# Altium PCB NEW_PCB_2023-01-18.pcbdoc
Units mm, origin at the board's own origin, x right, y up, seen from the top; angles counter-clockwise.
Board outline 125.93 x 125.98 mm, 2 copper layers (Top Layer, Bottom Layer); 36 components, 59 nets, 178 pads, 4 vias.
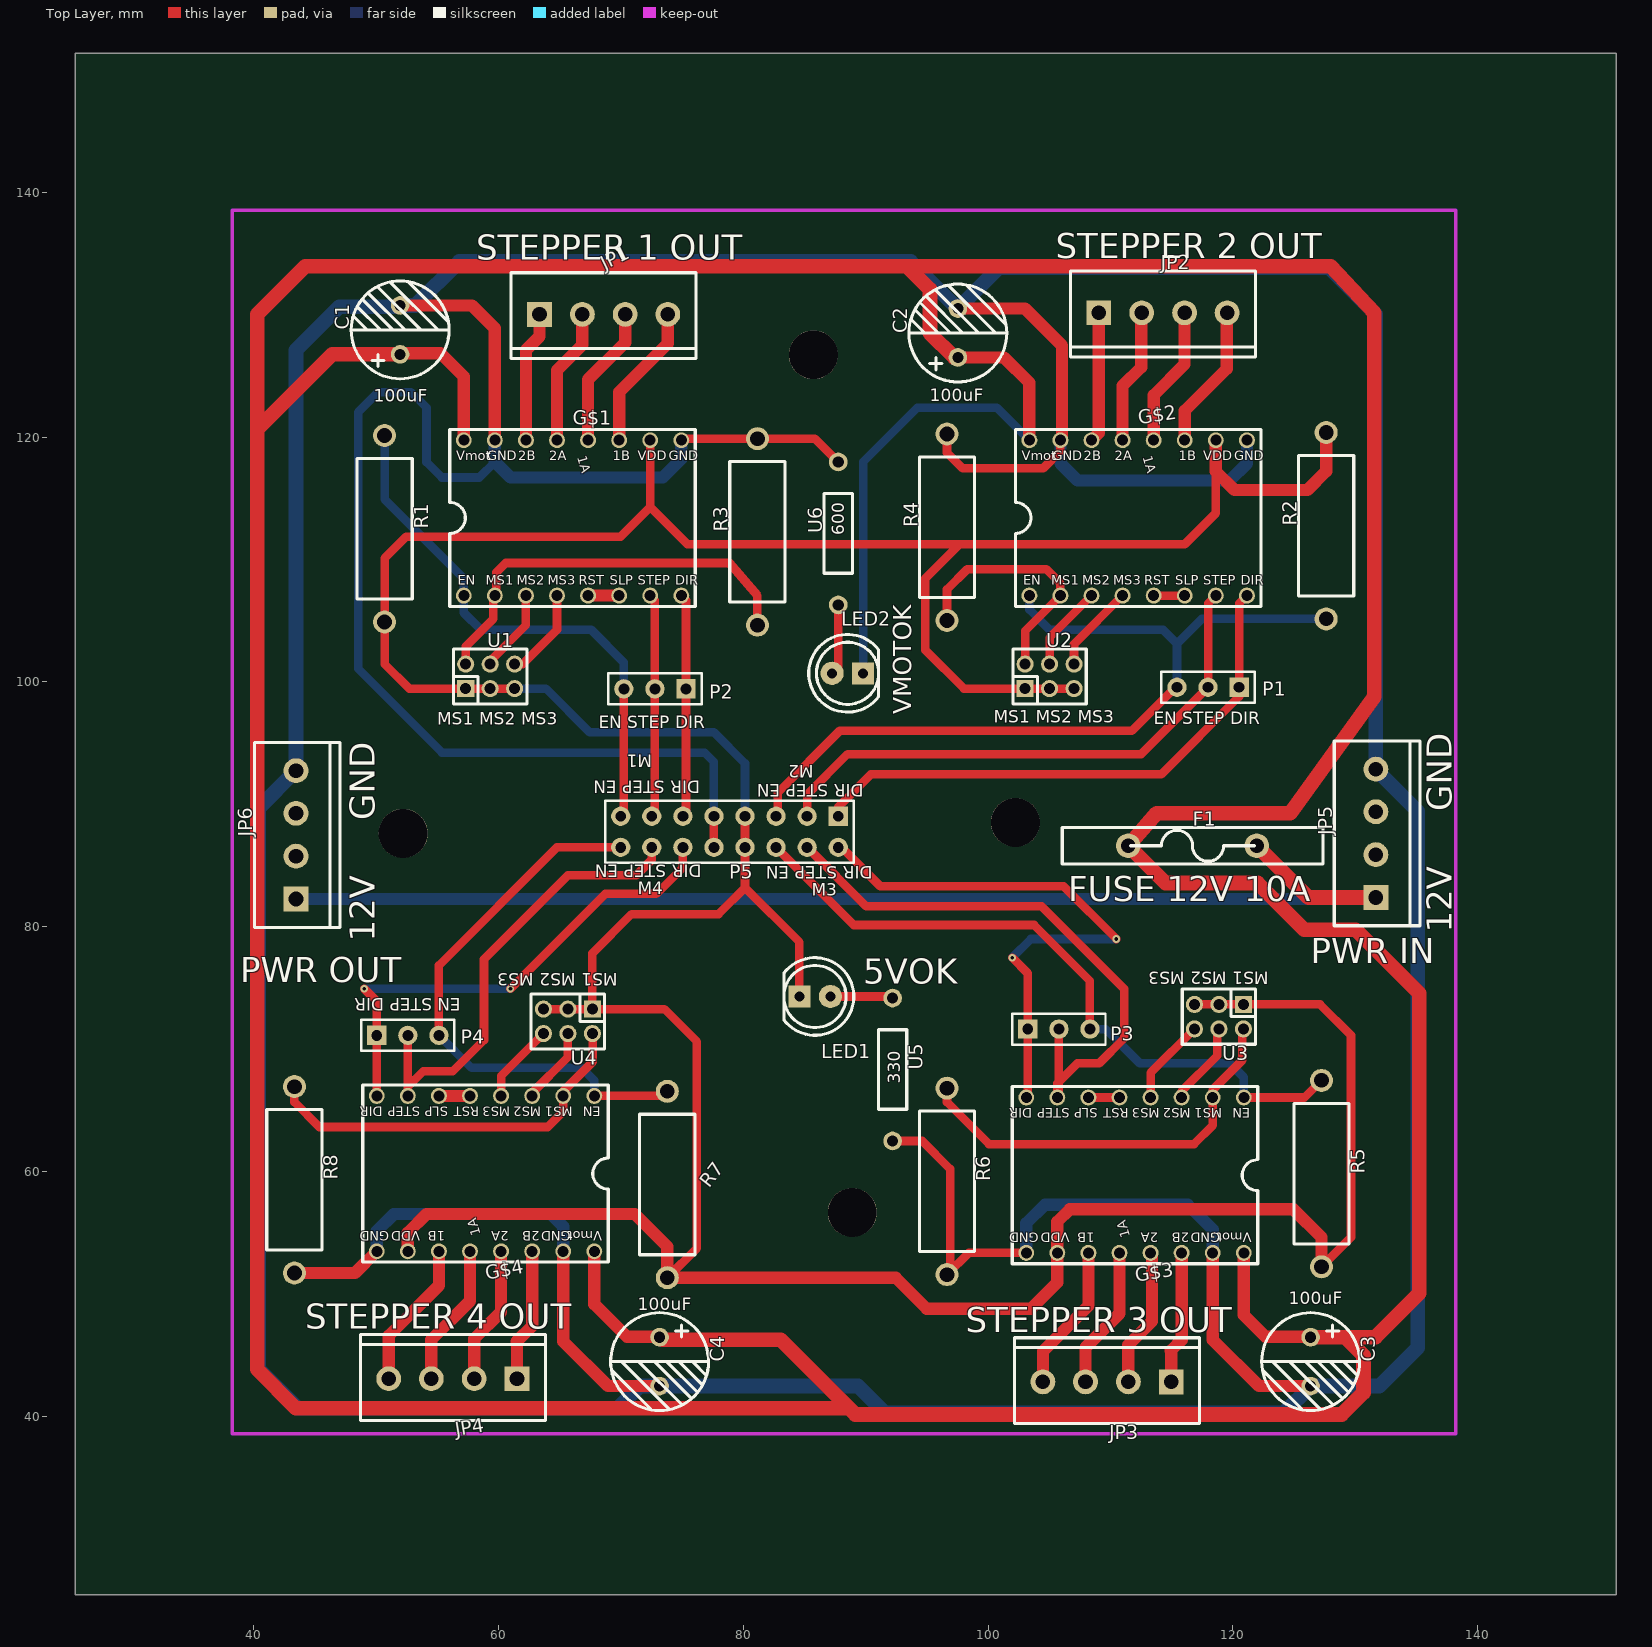
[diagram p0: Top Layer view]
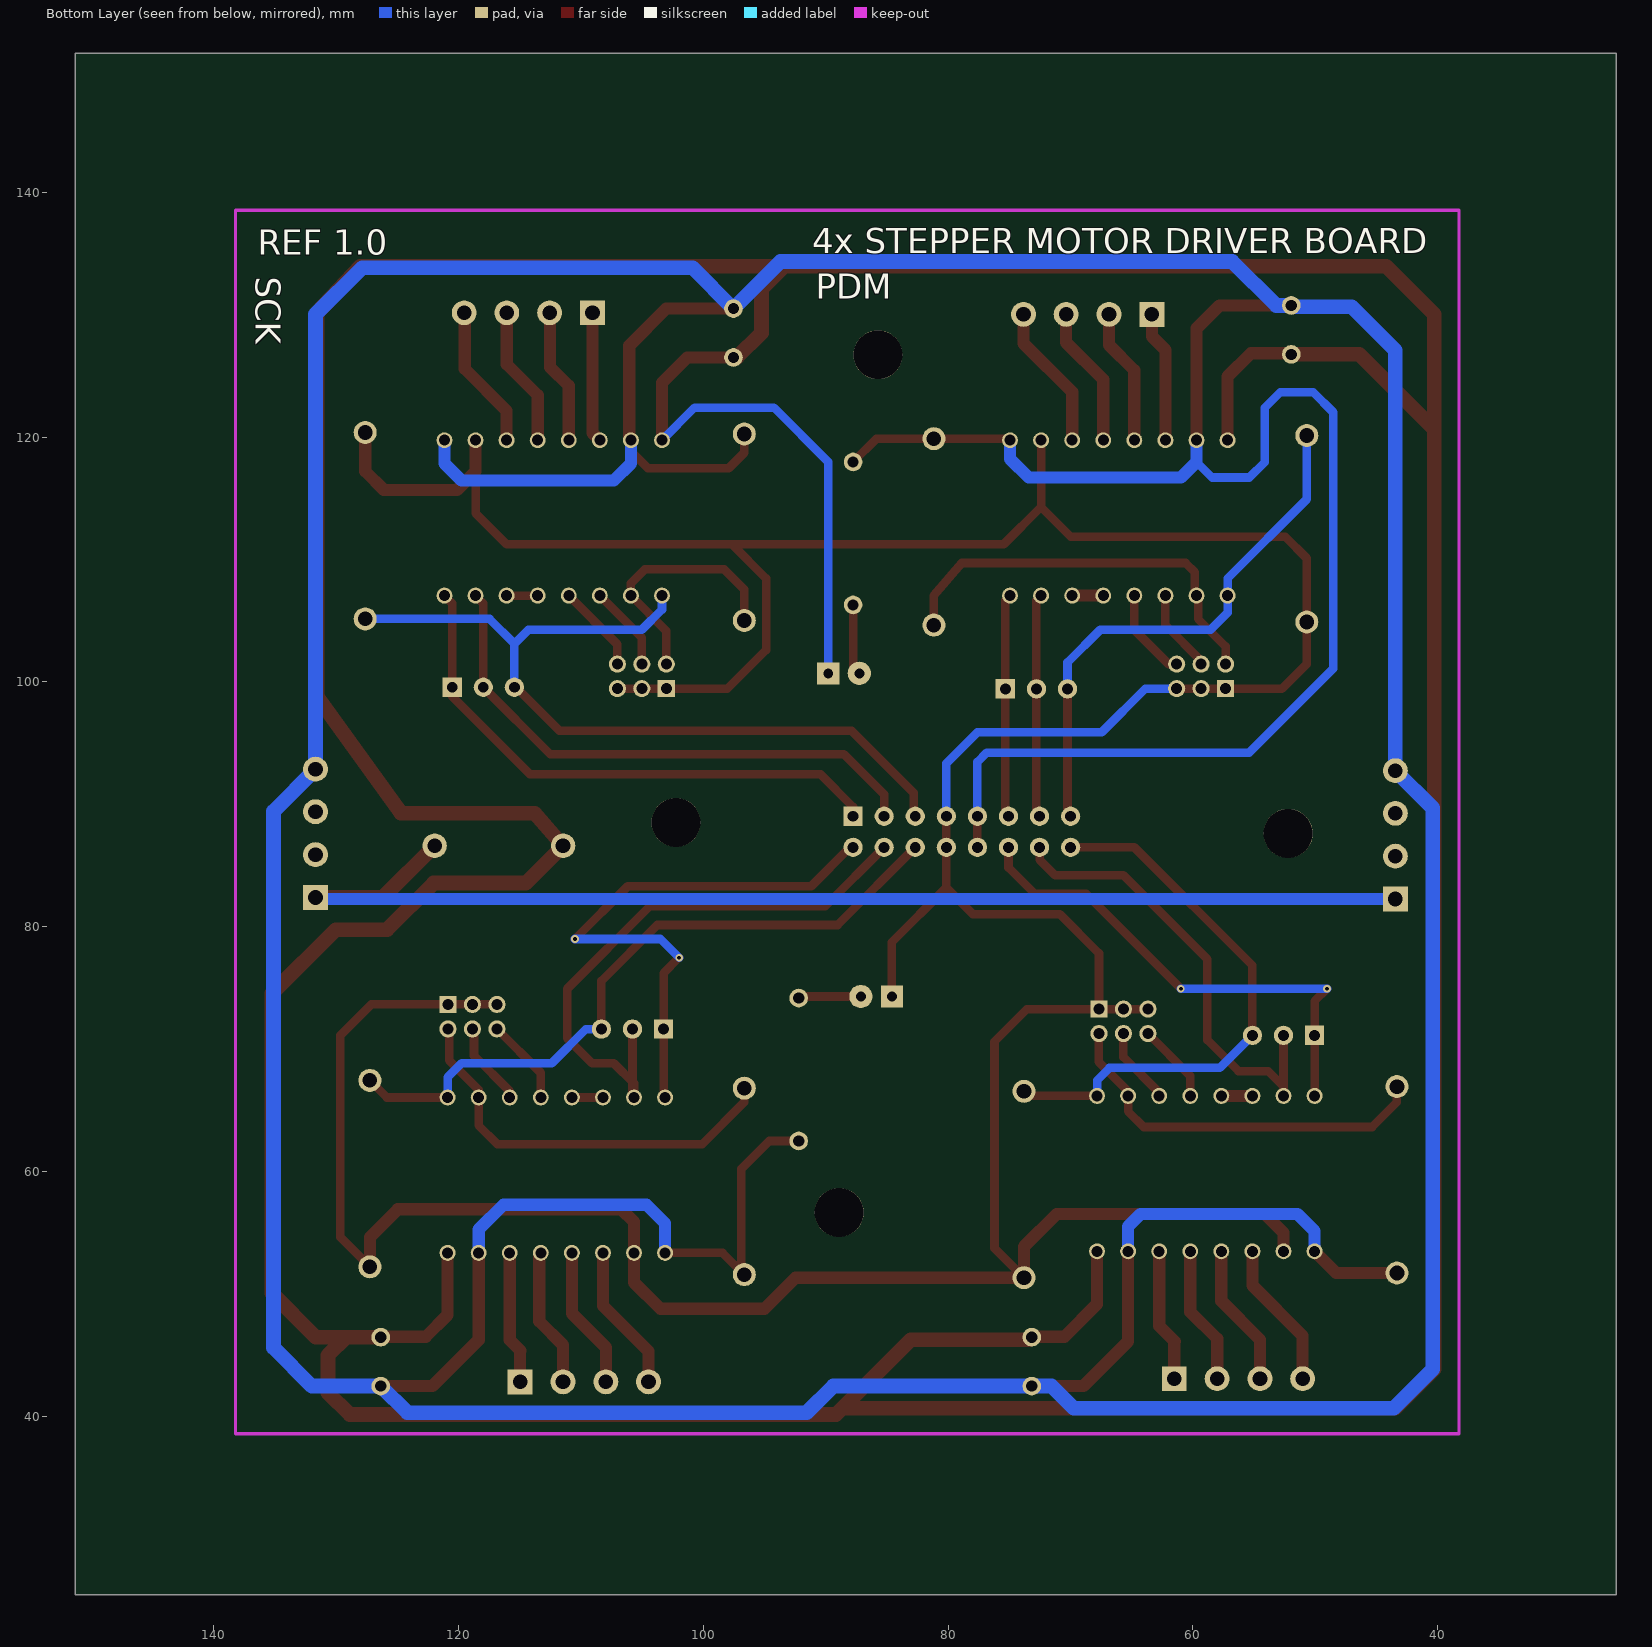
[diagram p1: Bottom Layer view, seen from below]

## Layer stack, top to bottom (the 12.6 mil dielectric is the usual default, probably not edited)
Top Layer: signal copper (thickness not stored)
Dielectric: dielectric 0.32, FR-4, Dk 4.8
Bottom Layer: signal copper (thickness not stored)

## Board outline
151.329,25.4 25.4,25.4 25.4,151.381 151.329,151.381

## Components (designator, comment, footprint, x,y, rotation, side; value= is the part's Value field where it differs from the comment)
C1 "100uF" CAP-8*5 51.943,128.775 r90 top
C2 "100uF" CAP-8*5 97.536,128.521 r90 top
C3 "100uF" CAP-8*5 126.365,44.447 r270 top
C4 "100uF" CAP-8*5 73.152,44.447 r270 top
F1 "fuseRXEF300" F-3.00A-60V 116.713,86.611 r0 top
G$1 "A4988" A4988BREAKOUT 58.42,118.488 r0 top
G$2 "A4988" A4988BREAKOUT 104.648,118.488 r0 top
G$3 "A4988" A4988BREAKOUT 119.634,54.607 r180 top
G$4 "A4988" A4988BREAKOUT 66.548,54.734 r180 top
JP1 "M04" SCREWTERMINAL-3.5MM-4 68.58,130.045 r0 top
JP2 "M04" SCREWTERMINAL-3.5MM-4 114.3,130.172 r0 top
JP3 "M04" SCREWTERMINAL-3.5MM-4 109.728,42.796 r180 top
JP4 "M04" SCREWTERMINAL-3.5MM-4 56.261,43.05 r180 top
JP5 "M04" SCREWTERMINAL-3.5MM-4 131.699,87.627 r90 top
JP6 "M04" SCREWTERMINAL-3.5MM-4 43.434,87.5 r90 top
LED1 "LED_5MM" "LED 5MM" 85.598,73.784 r180 top
LED2 "LED_5MM" "LED 5MM" 88.773,101.216 r0 top
P1 "Header-Male-2.54_1x3" HDR-3X1/2.54 117.983,99.565 r180 top
P2 "Header-Male-2.54_1x3" HDR-3X1/2.54 72.771,99.438 r180 top
P3 "Header-Male-2.54_1x3" HDR-3X1/2.54 105.791,71.625 r0 top
P4 "Header-Male-2.54_1x3" HDR-3X1/2.54 52.578,71.117 r0 top
P5 "Header-Male-2.54_2x8" HDR-8X2/2.54 78.867,87.754 r180 top
R1 "10k" AXIAL-0.6 50.673,112.519 r270 top
R2 "10k" AXIAL-0.6 127.635,112.773 r90 top
R3 "100k" AXIAL-0.6 81.153,112.265 r90 top
R4 "100k" AXIAL-0.6 96.647,112.646 r90 top
R5 "10k" AXIAL-0.6 127.254,59.814 r270 top
R6 "100k" AXIAL-0.6 96.647,59.179 r270 top
R7 "10k" AXIAL-0.6 73.787,58.925 r270 top
R8 "100k" AXIAL-0.6 43.307,59.306 r270 top
U1 "2*3P" HDR-2.0-2X3P 59.309,100.454 r0 top
U2 "2*3P" HDR-2.0-2X3P 105.029,100.454 r0 top
U3 "2*3P" HDR-2.0-2X3P 118.872,72.641 r180 top
U4 "2*3P" HDR-2.0-2X3P 65.659,72.26 r180 top
U5 "RF25CT52A331J" AXIAL-6.5X2.3(1/4W) 92.202,68.323 r270 top
U6 "RF25CT52A331J" AXIAL-6.5X2.3(1/4W) 87.757,112.138 r90 top

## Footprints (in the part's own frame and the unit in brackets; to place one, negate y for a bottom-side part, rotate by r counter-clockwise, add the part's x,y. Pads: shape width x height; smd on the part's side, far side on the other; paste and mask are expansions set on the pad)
A4988BREAKOUT [mm]
  round 1.3 hole 0.899: 1A(8.89,1.27) 1B(11.43,1.27) 2A(6.35,1.27) 2B(3.81,1.27) DIR(16.51,-11.43) EN(-1.27,-11.43) GND(16.51,1.27) GND@0(1.27,1.27) MS1(1.27,-11.43) MS2(3.81,-11.43) MS3(6.35,-11.43) RST(8.89,-11.43) SLP(11.43,-11.43) STEP(13.97,-11.43) VDD(13.97,1.27) VMOT(-1.27,1.27)
  silkscreen extent -2.41,-12.32 17.65,2.16
AXIAL-0.6 [mil]
  round 74 hole 47.2: 1(-300,0) 2(300,0)
  silkscreen extent -226,-89 226,89
AXIAL-6.5X2.3(1/4W) [mil]
  round 60 hole 36: 1(-230,0) 2(230,0)
  silkscreen extent -128,-45 128,45
CAP-8*5 [mil]
  round 60 hole 36: 1(-78.7,0) 2(78.7,0)
  silkscreen extent -158,-158 158,158
F-3.00A-60V [mm]
  round 2 hole 1.2: 1(-5.25,0) 2(5.25,0)
  silkscreen extent -10.65,-1.5 10.65,1.5
HDR-2.0-2X3P [mm]
  rect 1.4x1.4 hole 0.9: 1(-2,-1)
  round 1.4 hole 0.9: 2(-2,1) 3(0,-1) 4(0,1) 5(2,-1) 6(2,1)
  silkscreen extent -3,-2.25 3,2.25
HDR-3X1/2.54 [mil]
  rect 62x62 hole 35: 1(-100,0)
  round 62 hole 35: 2(0,0) 3(100,0)
  silkscreen extent -150,-50 150,50
HDR-8X2/2.54 [mil]
  rect 62x62 hole 35: 1(-350,-50)
  round 62 hole 35: 2(-350,50) 3(-250,-50) 4(-250,50) 5(-150,-50) 6(-150,50) 7(-50,-50) 8(-50,50) 9(50,-50) 10(50,50) 11(150,-50) 12(150,50) 13(250,-50) 14(250,50) 15(350,-50) 16(350,50)
  silkscreen extent -400,-100 400,100
"LED 5MM" [mm]
  round 1.9 hole 0.813: 1(-1.524,-0.508)
  rect 1.8x1.8 hole 0.813: 2(1.016,-0.507)
  silkscreen extent -3.42,-3.68 2.29,2.66
SCREWTERMINAL-3.5MM-4 [mil]
  rect 80x80 hole 47.2: 1(-206.5,0)
  round 80 hole 47.2: 2(-68.5,0) 3(69.5,0) 4(206.5,0)
  silkscreen extent -298,-142 298,134

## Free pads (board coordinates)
  round 4 hole 4 unplated: ""(52.197,87.627) ""(85.725,126.743) ""(88.9,56.639) ""(102.235,88.516)

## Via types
v1: diameter 0.62, hole 0.305, Top Layer to Bottom Layer, tented both sides, 4 vias

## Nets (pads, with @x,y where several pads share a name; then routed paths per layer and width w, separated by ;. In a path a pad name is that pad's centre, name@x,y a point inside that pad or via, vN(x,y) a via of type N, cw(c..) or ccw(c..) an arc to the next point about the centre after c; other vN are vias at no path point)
+5V: G$1.VDD G$2.VDD G$3.VDD G$4.VDD LED1.2 P5.7 P5.8 R1.2 R2.2 R5.2 R7.2 U1.1 U1.3 U1.5 U2.1 U2.3 U2.5 U3.1 U3.3 U3.5 U4.1 U4.3 U4.5 | length 381.6
  Top Layer w0.7: U1.5 U1.3 U1.1 52.721,99.454 52.705,99.438 50.673,101.47 R1.2 50.673,110.106 52.451,111.884 69.977,111.884 72.39,114.297 ; U4.5 U4.3 U4.1 ; G$1.VDD 72.39,114.297 ; R7.2 76.2,53.718 76.2,70.609 73.549,73.26 U4.1 ; P5.7 P5.8 80.137,83.182 ; LED1.2 84.582,78.738 80.137,83.182 ; U2.5 U2.3 U2.1 98.028,99.454 94.869,102.613 94.869,108.455 97.663,111.249 116.078,111.249 ; U3.5 U3.3 U3.1 127.143,73.641 129.667,71.117 129.667,54.607 R5.2 ; G$2.VDD 118.618,113.789 116.078,111.249 ; U4.1 67.659,77.816 67.691,77.848 70.866,81.023 77.978,81.023 80.137,83.182 ; 72.39,114.297 75.438,111.249 116.078,111.249
  Top Layer w1: G$4.VDD 52.578,54.988 54.102,56.512 71.12,56.512 73.787,53.845 R7.2 92.456,51.305 94.996,48.765 103.505,48.765 105.664,50.924 G$3.VDD 105.664,55.877 106.68,56.893 124.968,56.893 127.254,54.607 R5.2 ; G$2.VDD 118.618,117.218 120.142,115.694 126.111,115.694 127.635,117.218 R2.2
  Bottom Layer w0.7: U1.5 63.865,99.454 67.437,95.882 77.597,95.882 80.137,93.342 P5.7
G$1_1A: G$1.1A JP1.3 | length 11.5
  Top Layer w1: G$1.1A 67.31,124.711 70.345,127.747 JP1.3
G$1_1B: G$1.1B JP1.4 | length 11.9
  Top Layer w1: G$1.1B 69.85,123.695 73.825,127.671 JP1.4
G$1_2A: G$1.2A JP1.2 | length 11.1
  Top Layer w1: G$1.2A 64.77,125.473 66.84,127.544 JP1.2
G$1_2B: G$1.2B JP1.1 | length 10.7
  Top Layer w1: G$1.2B 62.23,127.124 63.335,128.229 JP1.1
G$1_DIR: G$1.DIR P2.1 P5.11 | length 18.3
  Top Layer w0.7: G$1.DIR 75.311,106.677 P2.1 75.311,89.278 P5.11
G$1_EN: G$1.EN P2.3 P5.15 R1.1 | length 44.6
  Top Layer w0.7: P5.15 70.231,89.278 P2.3
  Bottom Layer w0.7: R1.1 50.673,114.932 57.15,108.455 G$1.EN 57.15,105.661 58.547,104.264 67.564,104.264 70.231,101.597 P2.3
G$1_MS1: G$1.MS1 R3.1 U1.2 | length 33.8
  Top Layer w0.7: U1.2 57.309,102.899 59.563,105.153 59.563,106.931 G$1.MS1 59.817,107.185 59.817,108.963 60.579,109.725 78.867,109.725 81.153,107.058 R3.1
G$1_MS2: G$1.MS2 U1.4 | length 6.8
  Top Layer w0.7: U1.4 59.309,101.724 62.23,104.645 G$1.MS2
G$1_MS3: G$1.MS3 U1.6 | length 7.4
  Top Layer w0.7: U1.6 61.96,101.454 64.77,104.264 G$1.MS3
G$1_RST: G$1.RST G$1.SLP | length 2.5
  Top Layer w1: G$1.RST G$1.SLP
G$1_STEP: G$1.STEP P2.2 P5.13 | length 18.3
  Top Layer w0.7: G$1.STEP 72.771,106.677 P2.2 72.771,89.278 P5.13
G$2_1A: G$2.1A JP2.3 | length 11.5
  Top Layer w1: G$2.1A 113.538,123.441 116.065,125.969 JP2.3
G$2_1B: G$2.1B JP2.4 | length 11.9
  Top Layer w1: G$2.1B 116.078,122.171 119.507,125.6 119.507,130.134 JP2.4
G$2_2A: G$2.2A JP2.2 | length 11.1
  Top Layer w1: G$2.2A 110.998,124.203 112.522,125.727 112.522,130.134 JP2.2
G$2_2B: G$2.2B JP2.1 | length 10.7
  Top Layer w1: G$2.2B 109.055,120.355 JP2.1
G$2_DIR: G$2.DIR P1.1 P5.1 | length 45.8
  Top Layer w0.7: P5.1 87.757,89.786 90.424,92.453 114.173,92.453 120.523,98.803 P1.1 120.523,106.423 G$2.DIR
G$2_EN: G$2.EN P1.3 P5.5 R2.1 | length 69.1
  Top Layer w0.7: P5.5 82.804,89.151 82.804,90.929 87.884,96.009 111.76,96.009 115.316,99.565 P1.3
  Bottom Layer w0.7: G$2.EN 103.378,105.915 105.029,104.264 114.3,104.264 115.443,103.121 ; P1.3 115.443,103.121 ; R2.1 117.475,105.153 115.443,103.121
G$2_MS1: G$2.MS1 R4.1 U2.2 | length 20.8
  Top Layer w0.7: R4.1 96.647,107.566 98.298,109.217 104.775,109.217 105.918,108.074 G$2.MS1 103.029,104.169 U2.2
G$2_MS2: G$2.MS2 U2.4 | length 7
  Top Layer w0.7: U2.4 105.029,103.629 G$2.MS2
G$2_MS3: G$2.MS3 U2.6 | length 7.2
  Top Layer w0.7: U2.6 107.029,103.089 G$2.MS3
G$2_RST: G$2.RST G$2.SLP | length 2.5
  Top Layer w0.7: G$2.RST G$2.SLP
G$2_STEP: G$2.STEP P1.2 P5.3 | length 45.9
  Top Layer w0.7: P5.3 85.217,90.802 88.519,94.104 112.522,94.104 P1.2 117.983,106.423 G$2.STEP
G$3_1A: G$3.1A JP3.3 | length 11.7
  Top Layer w1: JP3.3 107.963,45.603 110.744,48.384 G$3.1A
G$3_1B: G$3.1B JP3.4 | length 12.1
  Top Layer w1: JP3.4 104.483,45.298 108.204,49.019 G$3.1B
G$3_2A: G$3.2A JP3.2 | length 11.4
  Top Layer w1: JP3.2 111.468,45.806 113.411,47.749 113.411,53.21 G$3.2A
G$3_2B: G$3.2B JP3.1 | length 10.9
  Top Layer w1: JP3.1 114.973,45.298 114.935,45.336 115.824,46.225 G$3.2B
G$3_DIR: G$3.DIR P3.1 P5.2 | length 47
  Top Layer w0.7: P5.2 88.011,86.484 91.186,83.309 106.172,83.309 v1(110.49,78.991) ; v1(101.981,77.467) 103.251,76.197 P3.1 103.251,66.164 G$3.DIR
  Bottom Layer w0.7: v1(101.981,77.467) 103.505,78.991 v1(110.49,78.991)
G$3_EN: G$3.EN P3.3 P5.6 R5.1 | length 56.9
  Top Layer w0.7: P5.6 89.027,80.134 103.759,80.134 108.331,75.562 P3.3 ; G$3.EN 125.857,66.037 R5.1
  Bottom Layer w0.7: P3.3 109.601,71.625 112.395,68.831 119.761,68.831 120.904,67.688 G$3.EN
G$3_MS1: G$3.MS1 R6.1 U3.2 | length 33.8
  Top Layer w0.7: R6.1 96.647,65.656 100.076,62.227 116.84,62.227 118.364,63.751 G$3.MS1 118.364,66.672 120.777,69.085 120.777,71.546 U3.2
G$3_MS2: G$3.MS2 U3.4 | length 6.9
  Top Layer w0.7: G$3.MS2 115.824,66.545 118.745,69.466 118.745,71.514 U3.4
G$3_MS3: G$3.MS3 U3.6 | length 7.1
  Top Layer w0.7: G$3.MS3 113.284,68.053 U3.6
G$3_RST: G$3.RST G$3.SLP | length 2.5
  Top Layer w0.7: G$3.SLP G$3.RST
G$3_STEP: G$3.STEP P3.2 P5.4 | length 48.5
  Top Layer w0.7: P5.4 90.043,81.658 104.394,81.658 111.125,74.927 111.125,70.863 109.093,68.831 107.315,68.831 105.664,67.18 G$3.STEP 105.791,66.164 P3.2
G$4_1A: G$4.1A JP4.3 | length 11.7
  Top Layer w1: JP4.3 54.496,46.238 57.658,49.4 G$4.1A
G$4_1B: G$4.1B JP4.4 | length 12.1
  Top Layer w1: JP4.4 51.016,46.568 55.118,50.67 G$4.1B
G$4_2A: G$4.2A JP4.2 | length 11.3
  Top Layer w1: JP4.2 58.001,46.314 60.198,48.511 G$4.2A
G$4_2B: G$4.2B JP4.1 | length 11
  Top Layer w1: JP4.1 61.506,46.06 61.468,46.098 62.738,47.368 G$4.2B
G$4_DIR: G$4.DIR P4.1 P5.12 | length 41
  Top Layer w0.7: v1(49.022,74.927) 50.038,73.911 P4.1 G$4.DIR ; v1(60.96,74.927) 68.707,82.674 72.898,82.674 75.057,84.833 P5.12
  Bottom Layer w0.7: v1(49.022,74.927) v1(60.96,74.927)
G$4_EN: G$4.EN P4.3 P5.16 R7.1 | length 46.2
  Top Layer w0.7: P4.3 55.118,76.832 64.77,86.484 P5.16 ; G$4.EN 73.406,66.164 R7.1
  Bottom Layer w0.7: P4.3 57.785,68.45 66.802,68.45 67.818,67.434 G$4.EN
G$4_MS1: G$4.MS1 R8.1 U4.2 | length 32
  Top Layer w0.7: R8.1 43.307,65.656 45.339,63.624 64.008,63.624 65.278,64.894 G$4.MS1 65.278,66.545 67.691,68.958 67.691,71.228 U4.2
G$4_MS2: G$4.MS2 U4.4 | length 6.3
  Top Layer w0.7: G$4.MS2 62.738,66.418 65.659,69.339 U4.4
G$4_MS3: G$4.MS3 U4.6 | length 6.5
  Top Layer w0.7: G$4.MS3 60.198,67.799 U4.6
G$4_RST: G$4.RST G$4.SLP | length 2.5
  Top Layer w1: G$4.SLP G$4.RST
G$4_STEP: G$4.STEP P4.2 P5.14 | length 38.2
  Top Layer w0.7: P4.2 G$4.STEP 52.578,66.926 53.848,68.196 56.261,68.196 58.801,70.736 58.801,77.34 65.659,84.198 71.247,84.198 72.517,85.468 P5.14
GND: C1.2 C2.2 C3.2 C4.2 G$1.GND G$1.GND@0 G$2.GND G$2.GND@0 G$3.GND G$3.GND@0 G$4.GND G$4.GND@0 JP5.4 JP6.4 P5.9 P5.10 R3.2 R4.2 R6.2 R8.2 U5.2 U6.2 | length 649.3
  Top Layer w0.7: G$1.GND 75.057,119.885 R3.2 85.852,119.885 U6.2 ; P5.10 P5.9 ; U5.2 94.615,62.481 96.901,60.195 96.901,51.813 R6.2 98.425,53.337 G$3.GND ; R4.2 96.647,118.742 97.917,117.472 104.521,117.472 105.918,118.869 105.918,119.758
  Top Layer w1: R8.2 48.26,51.686 G$4.GND ; C1.2 57.818,130.774 59.69,128.902 59.69,119.758 ; 65.278,53.464 65.278,46.098 68.928,42.448 C4.2 ; C2.2 103.03,130.52 106.045,127.505 106.045,119.885 105.918,119.758 ; 118.364,53.337 118.364,46.225 122.141,42.448 C3.2
  Bottom Layer w0.7: 59.69,117.98 58.42,116.71 55.372,116.71 54.102,117.98 54.102,122.425 52.832,123.695 50.165,123.695 48.514,122.044 48.514,101.089 55.372,94.231 76.835,94.231 77.597,93.469 P5.9
  Bottom Layer w1: G$4.GND 50.038,55.115 51.435,56.512 64.262,56.512 65.278,55.496 65.278,53.464 ; 59.69,119.758 59.69,117.98 60.96,116.71 73.406,116.71 74.93,118.234 G$1.GND ; G$3.GND 103.124,55.75 104.648,57.274 116.332,57.274 118.364,55.242 118.364,53.337 ; 105.918,119.758 105.918,117.853 107.315,116.456 119.761,116.456 121.158,117.853 G$2.GND
  Bottom Layer w1.2: 40.386,43.812 43.561,40.637 69.723,40.637 71.534,42.448 C4.2 89.375,42.448 91.567,40.256 124.173,40.256 C3.2 131.986,42.448 135.128,45.59 135.128,89.444 JP5.4 131.699,130.045 127.889,133.855 100.871,133.855 C2.2 93.693,134.363 56.769,134.363 53.18,130.774 C1.2 51.849,130.68 46.99,130.68 43.434,127.124 JP6.4 40.386,89.698 40.386,43.812
JP5_1: F1.2 JP5.1 JP6.1 | length 99.8
  Top Layer w1.2: F1.2 126.192,82.382 JP5.1
  Bottom Layer w1: JP6.1 131.572,82.255 JP5.1
JP5_2: JP5.2
JP5_3: JP5.3
JP6_2: JP6.2
JP6_3: JP6.3
LED1_1: LED1.1 U5.1 | length 5.1
  Top Layer w0.7: LED1.1 92.075,74.292 U5.1
LED2_1: LED2.1 U6.1 | length 5.8
  Top Layer w0.7: LED2.1 87.757,101.216 U6.1
S$6: 
S$8: 
S$41: 
S$43: 
S$47: 
VCC: C1.1 C2.1 C3.1 C4.1 F1.1 G$1.VMOT G$2.VMOT G$3.VMOT G$4.VMOT LED2.2 | length 523.4
  Top Layer w1: C1.1 52.037,126.87 55.245,126.87 57.15,124.965 G$1.VMOT ; G$4.VMOT 67.818,49.146 70.485,46.479 73.119,46.479 C4.1 ; C2.1 101.313,126.522 103.378,124.457 G$2.VMOT ; G$3.VMOT 120.904,48.257 122.682,46.479 126.332,46.479 C3.1
  Top Layer w1.2: C1.1 46.388,126.776 40.259,120.647 ; C4.1 73.373,46.225 83.058,46.225 89.154,40.129 ; 93.37,133.982 95.25,132.102 95.25,128.521 97.249,126.522 C2.1 ; 40.259,120.647 40.259,43.812 43.434,40.637 88.646,40.637 89.154,40.129 ; 40.259,120.647 40.259,130.045 44.196,133.982 95.377,133.982 128.016,133.982 131.572,130.172 131.572,98.803 124.714,89.278 120.142,89.278 113.792,89.278 F1.1 114.511,83.563 122.047,83.563 125.857,79.753 130.048,79.753 135.255,74.546 135.255,50.035 131.666,46.446 C3.1 129.192,46.446 130.683,44.955 130.683,41.907 128.905,40.129 89.154,40.129
  Bottom Layer w0.7: LED2.2 89.789,117.981 94.234,122.425 100.711,122.425 G$2.VMOT

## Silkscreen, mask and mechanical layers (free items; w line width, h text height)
Top Overlay:
  text "STEPPER 2 OUT" at 105.537,134.617 h2.03
  text "STEPPER 1 OUT" at 58.166,134.526 h2.03
  text "100uF" at 95.25,122.941 h1
  text "100uF" at 49.784,122.903 h1
  text "600" at 88.257,111.973 h1 r90
  text "VMOTOK" at 93.714,97.351 h1.5 r90
  text "MS1 MS2 MS3" at 100.457,96.652 h1
  text "EN STEP DIR" at 113.538,96.525 h1
  text "MS1 MS2 MS3" at 54.991,96.487 h1
  text "EN STEP DIR" at 68.199,96.233 h1
  text "M1" at 72.555,94.069 h1 r180
  text "M2" at 85.738,93.18 h1 r180
  text "DIR STEP EN" at 76.492,91.91 h1 r180
  text "DIR STEP EN" at 89.827,91.656 h1 r180
  text "DIR STEP EN" at 76.619,85.052 h1 r180
  text "DIR STEP EN" at 90.589,84.925 h1 r180
  text "M4" at 71.374,82.644 h1
  text "M3" at 85.598,82.517 h1
  text "FUSE 12V 10A" at 106.553,82.075 h2.03
  text "12V     GND" at 137.922,79.499 h2.03 r90
  text "12V     GND" at 49.875,78.773 h2.03 r90
  text "PWR IN" at 126.365,76.995 h2.03
  text "MS1 MS2 MS3" at 122.936,76.316 h1 r180
  text "MS1 MS2 MS3" at 69.723,76.189 h1 r180
  text "PWR OUT" at 38.862,75.471 h2.03
  text "5VOK" at 89.789,75.344 h2.03
  text "EN STEP DIR" at 56.896,74.157 h1 r180
  text "330" at 92.829,67.142 h1 r90
  text "100uF" at 124.587,49.154 h1
  text "100uF" at 71.374,48.646 h1
  text "STEPPER 4 OUT" at 44.196,47.114 h2.03
  text "STEPPER 3 OUT" at 98.171,46.86 h2.03
Bottom Overlay:
  text "4x STEPPER MOTOR DRIVER BOARD" at 91.117,135.033 h2.03
  text "REF 1.0" at 136.437,134.906 h2.03
  text "SCK" at 136.597,133.128 h2.03 r90
  text "PDM" at 90.805,131.315 h2.03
